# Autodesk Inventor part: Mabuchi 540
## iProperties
Created: 2010-04
Part Number: Mabuchi 540
Document SubType Name: Modeling
Designer: Mats
Mass: 170 g
Surface Area: 82.2006 cm^2
Volume: 51.0187 cm^3
Density: 1 g/cm^3
Author: Mats
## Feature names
1. Extrusion1
2. Extrusion2
3. Extrusion3
4. Fillet1
5. Extrusion4
6. Fillet2
7. Extrusion5
8. Hole1
9. Fillet3
